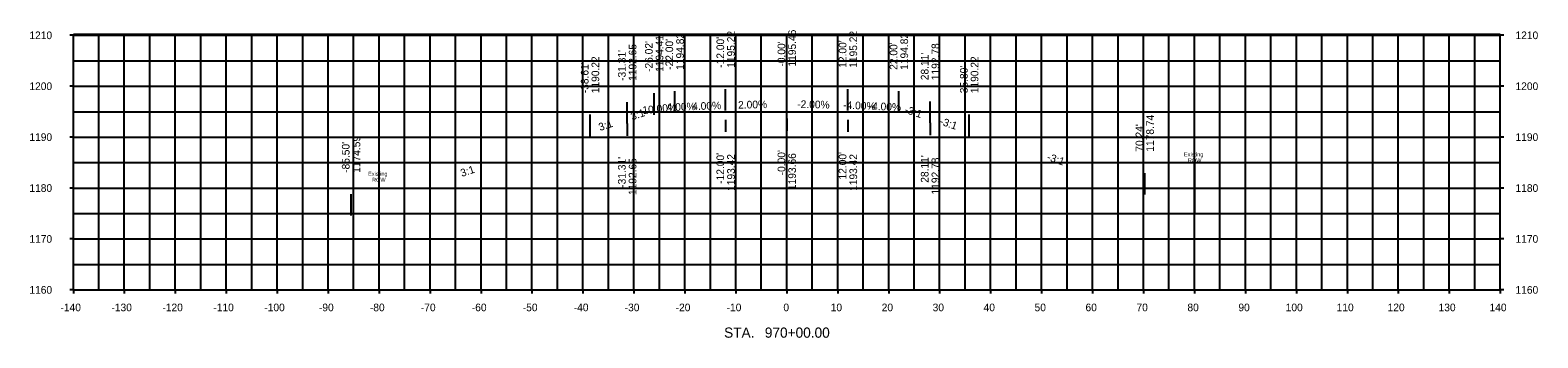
# Model space of a CAD drawing. Extents: x -148 to 147, y 1151 to 1211.
import ezdxf

# ---------------------------------------------------------------- set-up
doc = ezdxf.new("R2010")
doc.units = 0
for name, color, linetype in [('_CIVIL_CONSTRUCTION', 7, 'Continuous'), ('Default', 7, 'Continuous'), ('DisROW Existing', 7, 'Continuous'), ('DisROW Property Lines', 7, 'Continuous'), ('ROWLines', 7, 'Continuous'), ('Topography', 7, 'Continuous')]:
    doc.layers.add(name, color=color, linetype=linetype)

msp = doc.modelspace()

# ---------------------------------------------------------------- linework, layer by layer
at = {"layer": '_CIVIL_CONSTRUCTION'}
for p, q in [((-130, 1160), (-130, 1210.25)), ((-120, 1160), (-120, 1210.25)), ((-110, 1160), (-110, 1210.25)), ((-100, 1160), (-100, 1210.25)), ((-90, 1160), (-90, 1210.25)), ((-80, 1160), (-80, 1210.25)), ((-70, 1160), (-70, 1210.25)), ((-60, 1160), (-60, 1210.25)), ((-50, 1160), (-50, 1210.25)), ((-40, 1160), (-40, 1210.25)), ((-30, 1160), (-30, 1210.25)), ((-20, 1160), (-20, 1210.25)), ((-10, 1160), (-10, 1210.25)), ((0, 1160), (0, 1210.25)), ((10, 1160), (10, 1210.25)), ((20, 1160), (20, 1210.25)), ((30, 1160), (30, 1210.25)), ((40, 1160), (40, 1210.25)), ((50, 1160), (50, 1210.25)), ((60, 1160), (60, 1210.25)), ((70, 1160), (70, 1210.25)), ((80, 1160), (80, 1210.25)), ((90, 1160), (90, 1210.25)), ((100, 1160), (100, 1210.25)), ((110, 1160), (110, 1210.25)), ((120, 1160), (120, 1210.25)), ((130, 1160), (130, 1210.25)), ((-140, 1210), (-140.72, 1210)), ((-140, 1210), (140, 1210)), ((140.72, 1210), (140, 1210)), ((-140, 1200), (-140.72, 1200)), ((-140, 1200), (140, 1200)), ((140.72, 1200), (140, 1200)), ((-140, 1190), (-140.72, 1190)), ((-140, 1190), (140, 1190)), ((140.72, 1190), (140, 1190)), ((-140, 1180), (-140.72, 1180)), ((-140, 1180), (140, 1180)), ((140.72, 1180), (140, 1180)), ((-140, 1170), (-140.72, 1170)), ((-140, 1170), (140, 1170)), ((140.72, 1170), (140, 1170)), ((-140, 1160), (-140.72, 1160)), ((-140, 1160), (-140, 1159.28)), ((-130, 1160), (-130, 1159.28)), ((-120, 1160), (-120, 1159.28)), ((-110, 1160), (-110, 1159.28)), ((-100, 1160), (-100, 1159.28)), ((-90, 1160), (-90, 1159.28)), ((-80, 1160), (-80, 1159.28)), ((-70, 1160), (-70, 1159.28)), ((-60, 1160), (-60, 1159.28)), ((-50, 1160), (-50, 1159.28)), ((-40, 1160), (-40, 1159.28)), ((-30, 1160), (-30, 1159.28)), ((-20, 1160), (-20, 1159.28)), ((-10, 1160), (-10, 1159.28)), ((0, 1160), (0, 1159.28)), ((10, 1160), (10, 1159.28)), ((20, 1160), (20, 1159.28)), ((30, 1160), (30, 1159.28)), ((40, 1160), (40, 1159.28)), ((50, 1160), (50, 1159.28)), ((60, 1160), (60, 1159.28)), ((70, 1160), (70, 1159.28)), ((80, 1160), (80, 1159.28)), ((90, 1160), (90, 1159.28)), ((100, 1160), (100, 1159.28)), ((110, 1160), (110, 1159.28)), ((120, 1160), (120, 1159.28)), ((130, 1160), (130, 1159.28)), ((140, 1160), (140, 1159.28)), ((140.72, 1160), (140, 1160))]:
    msp.add_line(p, q, dxfattribs=at)
at = {"layer": 'DisROW Existing'}
for p, q in [((-26.02, 1194.41), (-26.02, 1198.61)), ((-22, 1194.82), (-22, 1199.02)), ((-12, 1195.22), (-12, 1199.42)), ((0, 1195.46), (0, 1199.66)), ((12, 1195.22), (12, 1199.42)), ((12, 1195.22), (12, 1199.42)), ((22, 1194.82), (22, 1199.02)), ((22, 1194.82), (22, 1199.02)), ((-31.31, 1192.65), (-31.31, 1196.85)), ((28.11, 1192.78), (28.11, 1196.98)), ((28.11, 1192.78), (28.11, 1196.98)), ((-38.61, 1190.22), (-38.61, 1194.42)), ((-31.31, 1192.65), (-31.31, 1190.25)), ((-12, 1193.42), (-12, 1191.02)), ((0, 1193.66), (0, 1191.26)), ((12, 1193.42), (12, 1191.02)), ((28.11, 1192.78), (28.11, 1190.38)), ((35.8, 1190.22), (35.8, 1194.42)), ((70.24, 1178.74), (70.24, 1182.94)), ((-85.5, 1174.59), (-85.5, 1178.79))]:
    msp.add_line(p, q, dxfattribs=at)
at = {"layer": 'DisROW Property Lines'}
for p, q in [((-135, 1160), (-135, 1210.25)), ((-125, 1160), (-125, 1210.25)), ((-115, 1160), (-115, 1210.25)), ((-105, 1160), (-105, 1210.25)), ((-95, 1160), (-95, 1210.25)), ((-85, 1160), (-85, 1210.25)), ((-75, 1160), (-75, 1210.25)), ((-65, 1160), (-65, 1210.25)), ((-55, 1160), (-55, 1210.25)), ((-45, 1160), (-45, 1210.25)), ((-35, 1160), (-35, 1210.25)), ((-25, 1160), (-25, 1210.25)), ((-15, 1160), (-15, 1210.25)), ((-5, 1160), (-5, 1210.25)), ((5, 1160), (5, 1210.25)), ((15, 1160), (15, 1210.25)), ((25, 1160), (25, 1210.25)), ((35, 1160), (35, 1210.25)), ((45, 1160), (45, 1210.25)), ((55, 1160), (55, 1210.25)), ((65, 1160), (65, 1210.25)), ((75, 1160), (75, 1210.25)), ((85, 1160), (85, 1210.25)), ((95, 1160), (95, 1210.25)), ((105, 1160), (105, 1210.25)), ((115, 1160), (115, 1210.25)), ((125, 1160), (125, 1210.25)), ((135, 1160), (135, 1210.25)), ((-140, 1205), (140, 1205)), ((-140, 1195), (140, 1195)), ((-140, 1185), (140, 1185)), ((-140, 1175), (140, 1175)), ((-140, 1165), (140, 1165))]:
    msp.add_line(p, q, dxfattribs=at)
at = {"layer": 'ROWLines'}
for p, q in [((-140, 1210.25), (140, 1210.25)), ((-140, 1160), (-140, 1210.25)), ((140, 1160), (140, 1210.25)), ((-140, 1160), (140, 1160))]:
    msp.add_line(p, q, dxfattribs=at)
at = {"layer": 'Topography'}
for p, q in [((80.04, 1184.88), (80.04, 1175.03)), ((-80.07, 1181.04), (-80.07, 1171.2))]:
    msp.add_line(p, q, dxfattribs=at)

# ---------------------------------------------------------------- texts
at = {"layer": 'Default'}
for s, height, p in [('1210', 1.5, (-148.63, 1209.25)), ('1210', 1.5, (143, 1209.25)), ('1200', 1.5, (-148.63, 1199.25)), ('1200', 1.5, (143, 1199.25)), ('1190', 1.5, (-148.63, 1189.25)), ('1190', 1.5, (143, 1189.25)), ('1180', 1.5, (-148.63, 1179.25)), ('1180', 1.5, (143, 1179.25)), ('1170', 1.5, (-148.63, 1169.25)), ('1170', 1.5, (143, 1169.25)), ('1160', 1.5, (-148.63, 1159.25)), ('1160', 1.5, (143, 1159.25)), ('-140', 1.5, (-142.53, 1155.8)), ('-130', 1.5, (-132.53, 1155.8)), ('-120', 1.5, (-122.53, 1155.8)), ('-110', 1.5, (-112.53, 1155.8)), ('-100', 1.5, (-102.53, 1155.8)), ('-90', 1.5, (-91.81, 1155.8)), ('-80', 1.5, (-81.81, 1155.8)), ('-70', 1.5, (-71.81, 1155.8)), ('-60', 1.5, (-61.81, 1155.8)), ('-50', 1.5, (-51.81, 1155.8)), ('-40', 1.5, (-41.81, 1155.8)), ('-30', 1.5, (-31.81, 1155.8)), ('-20', 1.5, (-21.81, 1155.8)), ('-10', 1.5, (-11.81, 1155.8)), ('0', 1.5, (-0.67, 1155.8)), ('10', 1.5, (8.62, 1155.8)), ('20', 1.5, (18.62, 1155.8)), ('30', 1.5, (28.62, 1155.8)), ('40', 1.5, (38.62, 1155.8)), ('50', 1.5, (48.62, 1155.8)), ('60', 1.5, (58.62, 1155.8)), ('70', 1.5, (68.62, 1155.8)), ('80', 1.5, (78.62, 1155.8)), ('90', 1.5, (88.62, 1155.8)), ('100', 1.5, (97.9, 1155.8)), ('110', 1.5, (107.9, 1155.8)), ('120', 1.5, (117.9, 1155.8)), ('130', 1.5, (127.9, 1155.8)), ('140', 1.5, (137.9, 1155.8)), ('STA.', 2.004, (-12.3, 1150.6)), ('970+00.00', 2.004, (-4.31, 1150.6))]:
    msp.add_text(s, height=height, dxfattribs=at).set_placement(p)
at = {"layer": 'DisROW Existing'}
for s, rotation, p in [('1194.82', 90, (-20.2, 1203.22)), ('1195.22', 90, (-10.2, 1203.62)), ('1195.46', 90, (1.8, 1203.86)), ('1195.22', 90, (13.8, 1203.62)), ('1195.22', 90, (13.8, 1203.62)), ('1194.82', 90, (23.8, 1203.22)), ('1194.82', 90, (23.8, 1203.22)), ('1192.65', 90, (-29.51, 1201.05)), ("-26.02'", 90, (-26.32, 1202.81)), ('1194.41', 90, (-24.22, 1202.81)), ("-22.00'", 90, (-22.3, 1203.22)), ("-12.00'", 90, (-12.3, 1203.62)), ("-0.00'", 90, (-0.3, 1203.86)), ("12.00'", 90, (11.7, 1203.62)), ("12.00'", 90, (11.7, 1203.62)), ("22.00'", 90, (21.7, 1203.22)), ("22.00'", 90, (21.7, 1203.22)), ('1192.78', 90, (29.91, 1201.18)), ('1192.78', 90, (29.91, 1201.18)), ("-38.61'", 90, (-38.91, 1198.62)), ('1190.22', 90, (-36.81, 1198.62)), ("-31.31'", 90, (-31.61, 1201.05)), ("28.11'", 90, (27.81, 1201.18)), ("28.11'", 90, (27.81, 1201.18)), ('1190.22', 90, (37.6, 1198.62)), ("35.80'", 90, (35.5, 1198.62)), ('3:1', 18.4332, (-30.35, 1193.3)), ('10.00%', 5.7106, (-28.25, 1194.52)), ('4.00%', 2.2906, (-23.54, 1195.08)), ('4.00%', 2.2906, (-18.54, 1195.28)), ('2.00%', 1.1458, (-9.54, 1195.59)), ('-2.00%', 358.8542, (2.04, 1195.74)), ('-4.00%', 357.7094, (11.04, 1195.58)), ('-4.00%', 357.7094, (16.04, 1195.38)), ('-3:1', 341.5668, (22.98, 1194.82)), ('3:1', 18.4332, (-36.65, 1191.2)), ('-3:1', 341.5668, (29.88, 1192.52)), ("70.24'", 90, (69.94, 1187.14)), ('1178.74', 90, (72.04, 1187.14)), ('1174.59', 90, (-83.7, 1182.99)), ("-85.50'", 90, (-85.8, 1182.99)), ("-12.00'", 90, (-12.3, 1180.83)), ('1193.42', 90, (-10.2, 1179.43)), ("-0.00'", 90, (-0.3, 1182.5)), ('1193.66', 90, (1.8, 1179.6)), ("12.00'", 90, (11.7, 1181.68)), ('1193.42', 90, (13.8, 1179.43)), ('-3:1', 341.5668, (50.94, 1185.5)), ('3:1', 18.4332, (-63.75, 1182.17)), ("-31.31'", 90, (-31.61, 1180.05)), ('1192.65', 90, (-29.51, 1178.62)), ("28.11'", 90, (27.81, 1181.04)), ('1192.78', 90, (29.91, 1178.73))]:
    msp.add_text(s, height=1.5, rotation=rotation, dxfattribs=at).set_placement(p)
at = {"layer": 'Topography'}
for s, p in [('Existing', (77.95, 1186.23)), ('ROW', (78.72, 1185.05)), ('Existing', (-82.16, 1182.4)), ('ROW', (-81.38, 1181.22))]:
    msp.add_text(s, height=0.787, dxfattribs=at).set_placement(p)

doc.saveas('drawing.dxf')
